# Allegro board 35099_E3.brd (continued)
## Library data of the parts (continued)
R240 R241 = RES: signal model: DEFAULT_RESISTOR_51000OHM_2_1
R243-R246 R248 R350 R353 R354 R356-R358 R360 R361 R365 R417-R422 = RES: signal model: RES_RC0402_25_DISCRETE_0.45_M_1_0
R249 R250 R362 R363 = RES: tolerance: 5%; signal model: DEFAULT_RESISTOR_10000OHM_2_1
R300-R307 R377-R380 R384-R398 = RES_3PIN: Tolerance: X; User Part Number: 470-80866; signal model: RES_3PIN_R603-X2_DISCRETE_0.6MM_0
RT1 = THERMISTOR: signal model: DEFAULT_RESISTOR_100000OHM_2_1
SH2-SH4 SH11-SH14 SH17-SH21 = RES_SHORT-2: signal model: DEFAULT_RESISTOR_0.001OHM_2_1
SW1-SW3 = SW_PB_4P
SW4 = SW_TC_SPST_4P
SW5 = SW_DIP-3
TP1-TP10 TP12-TP14 TP16 TP18 TP21-TP34 TP37-TP46 = TEST POINT L
TP11 TP15 TP17 TP19 TP20 = TESTLOOP
U1 = LPC432_BGA_100P
U2 U5 U10 U27 U28 = 74LVCH1T45_6P
U3 U26 = 74AVC2T45_8P
U4 U9 = 74AVC4TD245BQ_DHVQFN16
U6 = FXOS8700CQ_QFN_16P
U7 = NX3DV2567GU_XQFN_16P
U8 = WM8904CGEFL_QFN32
U12 U17 = TFA9894D_48P
U13 = NX5P3090UK_WLCSP12
U14 = LD1117AS18
U15 = 2-input_or
U16 U30 = NC7SZ14
U18 = MIMXRT685EVKA_176P
U19 = MX25UM51345GXD
U20 = PCA9420KBS_HVQFN24
U21 U22 = PRTR5V0U2X
U23 U25 = NCP692_6P
U24 = 74LVC07APW
U32 = 74LVC2G07
U34 = NTB0104BQ
U35 = NTB0102DP
U36 = NTS0102
U40 U41 = MIC_SPH0641LM4H-1_5P
U108 = APS6408L-OBx_BGA24L
Y1 = XTAL
Y2 = XTAL_13
Y3 = CRYSTAL
Y8 = OSC_ASFL

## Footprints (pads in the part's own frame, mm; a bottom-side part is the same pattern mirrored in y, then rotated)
0402_CC
  rect 0.457x0.508 smd: 1(-0.375,0) 2(0.375,0)
0603_CC
  rect 0.711x0.838 smd: 1(-0.65,0) 2(0.65,0)
BGA176_0P5_9X9
  round 0.229 smd: A1(-4,4) A2(-3.5,4) A3(-3,4) A5(-2,4) A7(-1,4) A9(0,4) A11(1,4) A13(2,4) A15(3,4) A16(3.5,4) A17(4,4) B1(-4,3.5) B2(-3.5,3.5) B3(-3,3.5) B5(-2,3.5) B6(-1.5,3.5) B7(-1,3.5) B9(0,3.5) B10(0.5,3.5) B11(1,3.5) B13(2,3.5) B14(2.5,3.5) B15(3,3.5) B16(3.5,3.5) B17(4,3.5) C1(-4,3) C2(-3.5,3) C3(-3,3) C4(-2.5,3) C5(-2,3) C7(-1,3) C9(0,3) C11(1,3) C13(2,3) C15(3,3) C16(3.5,3) C17(4,3) D2(-3.5,2.5) D5(-2,2.5) D6(-1.5,2.5) D7(-1,2.5) D8(-0.5,2.5) D9(0,2.5) D11(1,2.5) D12(1.5,2.5) D13(2,2.5) D15(3,2.5) E1(-4,2) E2(-3.5,2) E3(-3,2) E4(-2.5,2) E6(-1.5,2) E8(-0.5,2) E10(0.5,2) E12(1.5,2) E14(2.5,2) E15(3,2) E16(3.5,2) E17(4,2) F4(-2.5,1.5) F5(-2,1.5) F7(-1,1.5) F11(1,1.5) F13(2,1.5) F14(2.5,1.5) F16(3.5,1.5) G1(-4,1) G2(-3.5,1) G3(-3,1) G4(-2.5,1) G6(-1.5,1) G12(1.5,1) G14(2.5,1) G15(3,1) G16(3.5,1) G17(4,1) H2(-3.5,0.5) H5(-2,0.5) H8(-0.5,0.5) H9(0,0.5) H10(0.5,0.5) H13(2,0.5) H14(2.5,0.5) J1(-4,0) J2(-3.5,0) J3(-3,0) J4(-2.5,0) J8(-0.5,0) J10(0.5,0) J14(2.5,0) J15(3,0) J16(3.5,0) J17(4,0) K4(-2.5,-0.5) K5(-2,-0.5) K8(-0.5,-0.5) K9(0,-0.5) K10(0.5,-0.5) K13(2,-0.5) K16(3.5,-0.5) L1(-4,-1) L2(-3.5,-1) L3(-3,-1) L4(-2.5,-1) L6(-1.5,-1) L12(1.5,-1) L14(2.5,-1) L15(3,-1) L16(3.5,-1) L17(4,-1) M2(-3.5,-1.5) M4(-2.5,-1.5) M5(-2,-1.5) M7(-1,-1.5) M11(1,-1.5) M13(2,-1.5) M14(2.5,-1.5) N1(-4,-2) N2(-3.5,-2) N3(-3,-2) N4(-2.5,-2) N6(-1.5,-2) N8(-0.5,-2) N10(0.5,-2) N12(1.5,-2) N14(2.5,-2) N15(3,-2) N16(3.5,-2) N17(4,-2) P3(-3,-2.5) P5(-2,-2.5) P6(-1.5,-2.5) P7(-1,-2.5) P9(0,-2.5) P10(0.5,-2.5) P11(1,-2.5) P12(1.5,-2.5) P13(2,-2.5) P16(3.5,-2.5) R1(-4,-3) R2(-3.5,-3) R3(-3,-3) R5(-2,-3) R7(-1,-3) R9(0,-3) R11(1,-3) R13(2,-3) R14(2.5,-3) R15(3,-3) R16(3.5,-3) R17(4,-3) T1(-4,-3.5) T2(-3.5,-3.5) T3(-3,-3.5) T4(-2.5,-3.5) T5(-2,-3.5) T7(-1,-3.5) T8(-0.5,-3.5) T9(0,-3.5) T11(1,-3.5) T12(1.5,-3.5) T13(2,-3.5) T15(3,-3.5) T16(3.5,-3.5) T17(4,-3.5) U1(-4,-4) U2(-3.5,-4) U3(-3,-4) U5(-2,-4) U7(-1,-4) U9(0,-4) U11(1,-4) U13(2,-4) U15(3,-4) U16(3.5,-4) U17(4,-4)
CC0201
  rect 0.47x0.381 smd: 1(-0.343,0) 2(0.343,0)
CC0402_25
  round 0.635 smd: 1(-0.508,0) 2(0.508,0)
CC0402_TOL0P2
  rect 0.457x0.61 smd: 1(-0.475,0) 2(0.475,0)
CC0603_0402_NSP
  rect 1.016x1.168 smd: 1(-0.699,0) 2(0.699,0)
CC0603_0805_NSP
  rect 1.549x1.549 smd: 1(-0.965,0) 2(0.965,0)
CC0603_OV
  oval 0.889x1.143 smd: 1(-0.762,0) 2(0.762,0)
CC1210
  rect 1.778x2.845 smd: 1(-1.397,0) 2(1.397,0)
CON2_TB_5MM_10X7P5MM_TH
  rect 2.159x2.159 hole 1.295: 1(0,0)
  round 2.159 hole 1.295: 2(5,0)
CON3_SKT_DC_POWER
  rect 2.235x2.235 hole 1.6: 1(0,0)
  round 2.235 hole 1.6: 2(3.1,5) 3(6.2,0)
CON4_JACK_5X17
  round 0.254 hole 1.702 unplated: (0,2.5) (0,-4.5)
  rect 2.794x2.21 smd: 1(-3.7,3.6) 3(3.7,1.6)
  rect 2.794x2.794 smd: 2(-3.7,-5.8) 4(0.753,-9.9)
CON9_MICROAB_USB_SHELL_TH
  rect 1.803x1.905 smd: (-1.15,0) (1.15,0)
  rect 0.406x1.346 smd: 1(-1.3,2.8) 2(-0.65,2.8) 3(0,2.8) 4(0.65,2.8) 5(1.3,2.8)
  oval 1.067x1.27 hole 0.66x0.864: 6(2.225,3.125) 9(-2.225,3.125)
  rect 2.21x1.905 hole 1.499x0.838: 7(4.175,0) 8(-4.175,0)
CON_1X8_SKT_2P54_TH
  rect 1.702x1.702 hole 1.016: 1(0,0)
  round 1.702 hole 1.016: 2(0,-2.54) 3(0,-5.08) 4(0,-7.62) 5(0,-10.16) 6(0,-12.7) 7(0,-15.24) 8(0,-17.78)
CON_67_0P5_22X7P75_RA
  rect 1.194x2.743 smd: (-10.35,3.125) (10.35,3.125)
  round 0.254 hole 1.092 unplated: (-10,-1.375)
  round 0.254 hole 1.6 unplated: (10,-1.375)
  rect 0.305x1.549 smd: 1(-9.25,3.9) 2(-9,-3.65) 3(-8.75,3.9) 4(-8.5,-3.65) 5(-8.25,3.9) 6(-8,-3.65) 7(-7.75,3.9) 8(-7.5,-3.65) 9(-7.25,3.9) 10(-7,-3.65) 11(-6.75,3.9) 12(-6.5,-3.65) 13(-6.25,3.9) 14(-6,-3.65) 15(-5.75,3.9) 16(-5.5,-3.65) 17(-5.25,3.9) 18(-5,-3.65) 19(-4.75,3.9) 20(-4.5,-3.65) 21(-4.25,3.9) 22(-4,-3.65) 23(-3.75,3.9) 32(-1.5,-3.65) 33(-1.25,3.9) 34(-1,-3.65) 35(-0.75,3.9) 36(-0.5,-3.65) 37(-0.25,3.9) 38(0,-3.65) 39(0.25,3.9) 40(0.5,-3.65) 41(0.75,3.9) 42(1,-3.65) 43(1.25,3.9) 44(1.5,-3.65) 45(1.75,3.9) 46(2,-3.65) 47(2.25,3.9) 48(2.5,-3.65) 49(2.75,3.9) 50(3,-3.65) 51(3.25,3.9) 52(3.5,-3.65) 53(3.75,3.9) 54(4,-3.65) 55(4.25,3.9) 56(4.5,-3.65) 57(4.75,3.9) 58(5,-3.65) 59(5.25,3.9) 60(5.5,-3.65) 61(5.75,3.9) 62(6,-3.65) 63(6.25,3.9) 64(6.5,-3.65) 65(6.75,3.9) 66(7,-3.65) 67(7.25,3.9) 68(7.5,-3.65) 69(7.75,3.9) 70(8,-3.65) 71(8.25,3.9) 72(8.5,-3.65) 73(8.75,3.9) 74(9,-3.65) 75(9.25,3.9)
CON_MIC_38M_25_SM
  round 0.254 hole 2.388 unplated: (11.43,0)
  rect 0.432x1.27 smd: 1(5.715,-3.556) 2(5.715,3.556) 3(5.08,-3.556) 4(5.08,3.556) 5(4.445,-3.556) 6(4.445,3.556) 7(3.81,-3.556) 8(3.81,3.556) 9(3.175,-3.556) 10(3.175,3.556) 11(2.54,-3.556) 12(2.54,3.556) 13(1.905,-3.556) 14(1.905,3.556) 15(1.27,-3.556) 16(1.27,3.556) 17(0.635,-3.556) 18(0.635,3.556) 19(0,-3.556) 20(0,3.556) 21(-0.635,-3.556) 22(-0.635,3.556) 23(-1.27,-3.556) 24(-1.27,3.556) 25(-1.905,-3.556) 26(-1.905,3.556) 27(-2.54,-3.556) 28(-2.54,3.556) 29(-3.175,-3.556) 30(-3.175,3.556) 31(-3.81,-3.556) 32(-3.81,3.556) 33(-4.445,-3.556) 34(-4.445,3.556) 35(-5.08,-3.556) 36(-5.08,3.556) 37(-5.715,-3.556) 38(-5.715,3.556)
  round 1.397 hole 0.889: S1(-5.08,0) S2(-2.54,0) S3(0,0) S4(2.54,0) S5(5.08,0)
CON_SDCARD_28P9X29_SM_RA
  round 0.254 hole 1.499 unplated: (-12.675,-9.05) (11.525,-9.05)
  rect 0.991x1.499 smd: 1(6.325,15.26) 2(3.825,15.26) 3(0.475,15.26) 4(-1.175,15.26) 5(-3.675,15.26) 6(-6.175,15.26) 7(-8.605,15.26) 8(-10.305,15.26) 9(8.825,15.26) 10(2.125,15.26) 11(-13.655,15.26)
  rect 1.194x2.007 smd: G1(-14.175,-6.95) G2(13.825,-5.75)
CON_SKT1X6_TH
  rect 1.524x1.524 hole 1.041: 1(0,0)
  round 1.524 hole 1.041: 2(0,-2.54) 3(0,-5.08) 4(0,-7.62) 5(0,-10.16) 6(0,-12.7)
CON_SKT1X9_TH
  rect 1.651x1.651 hole 1.016: 1(0,0)
  round 1.651 hole 1.016: 2(0,-2.54) 3(0,-5.08) 4(0,-7.62) 5(0,-10.16) 6(0,-12.7) 7(0,-15.24) 8(0,-17.78) 9(0,-20.32)
DFN6_0P95_3X3
  rect 0.889x0.457 smd: 1(-1.469,0.95) 2(-1.469,0) 3(-1.469,-0.95) 4(1.469,-0.95) 5(1.469,0) 6(1.469,0.95)
  rect 1.676x2.591 smd: 7(0,0)
DFN1010N-6_0P35_1P15X1P05
  rect 0.356x0.178 smd: 1(-0.433,0.35) 2(-0.433,0) 3(-0.433,-0.35) 4(0.433,-0.35) 5(0.433,0) 6(0.433,0.35)
  rect 0.254x0.406 smd: 7(0,0.275) 8(0,-0.275)
DHVQFN14_3X2P5MM
  rect 0.914x0.279 smd: 1(-1.55,-0.25) 7(1.55,-0.25) 8(1.55,0.25) 14(-1.55,0.25)
  rect 0.279x0.914 smd: 2(-1,-1.3) 3(-0.5,-1.3) 4(0,-1.3) 5(0.5,-1.3) 6(1,-1.3) 9(1,1.3) 10(0.5,1.3) 11(0,1.3) 12(-0.5,1.3) 13(-1,1.3)
  rect 1.651x1.143 smd: 15(0,0)
DHVQFN16_0P5_3P6X2P6
  rect 0.305x0.838 smd: 1(-0.25,1.719) 8(-0.25,-1.719) 9(0.25,-1.719) 16(0.25,1.719)
  rect 0.838x0.305 smd: 2(-1.219,1.25) 3(-1.219,0.75) 4(-1.219,0.25) 5(-1.219,-0.25) 6(-1.219,-0.75) 7(-1.219,-1.25) 10(1.219,-1.25) 11(1.219,-0.75) 12(1.219,-0.25) 13(1.219,0.25) 14(1.219,0.75) 15(1.219,1.25)
  rect 1.143x2.159 smd: 17(0,0)
FBGA100_0P8_9X9
  round 0.406 smd: A1(-3.6,3.6) A2(-2.8,3.6) A3(-2,3.6) A4(-1.2,3.6) A5(-0.4,3.6) A6(0.4,3.6) A7(1.2,3.6) A8(2,3.6) A9(2.8,3.6) A10(3.6,3.6) B1(-3.6,2.8) B2(-2.8,2.8) B3(-2,2.8) B4(-1.2,2.8) B5(-0.4,2.8) B6(0.4,2.8) B7(1.2,2.8) B8(2,2.8) B9(2.8,2.8) B10(3.6,2.8) C1(-3.6,2) C2(-2.8,2) C3(-2,2) C4(-1.2,2) C5(-0.4,2) C6(0.4,2) C7(1.2,2) C8(2,2) C9(2.8,2) C10(3.6,2) D1(-3.6,1.2) D2(-2.8,1.2) D3(-2,1.2) D4(-1.2,1.2) D5(-0.4,1.2) D6(0.4,1.2) D7(1.2,1.2) D8(2,1.2) D9(2.8,1.2) D10(3.6,1.2) E1(-3.6,0.4) E2(-2.8,0.4) E3(-2,0.4) E4(-1.2,0.4) E5(-0.4,0.4) E6(0.4,0.4) E7(1.2,0.4) E8(2,0.4) E9(2.8,0.4) E10(3.6,0.4) F1(-3.6,-0.4) F2(-2.8,-0.4) F3(-2,-0.4) F4(-1.2,-0.4) F5(-0.4,-0.4) F6(0.4,-0.4) F7(1.2,-0.4) F8(2,-0.4) F9(2.8,-0.4) F10(3.6,-0.4) G1(-3.6,-1.2) G2(-2.8,-1.2) G3(-2,-1.2) G4(-1.2,-1.2) G5(-0.4,-1.2) G6(0.4,-1.2) G7(1.2,-1.2) G8(2,-1.2) G9(2.8,-1.2) G10(3.6,-1.2) H1(-3.6,-2) H2(-2.8,-2) H3(-2,-2) H4(-1.2,-2) H5(-0.4,-2) H6(0.4,-2) H7(1.2,-2) H8(2,-2) H9(2.8,-2) H10(3.6,-2) J1(-3.6,-2.8) J2(-2.8,-2.8) J3(-2,-2.8) J4(-1.2,-2.8) J5(-0.4,-2.8) J6(0.4,-2.8) J7(1.2,-2.8) J8(2,-2.8) J9(2.8,-2.8) J10(3.6,-2.8) K1(-3.6,-3.6) K2(-2.8,-3.6) K3(-2,-3.6) K4(-1.2,-3.6) K5(-0.4,-3.6) K6(0.4,-3.6) K7(1.2,-3.6) K8(2,-3.6) K9(2.8,-3.6) K10(3.6,-3.6)
HDR1X2_2P0_5P9X7P6
  rect 1.651x1.651 hole 1.016: 1(0,0)
  round 1.651 hole 1.016: 2(2,0)
HDR102
  rect 1.524x1.524 hole 1.016: 1(0,0)
  round 1.524 hole 1.016: 2(0,-2.54)
HDR103
  rect 1.524x1.524 hole 1.016: 1(0,0)
  round 1.524 hole 1.016: 2(0,-2.54) 3(0,-5.08)
HDR110
  rect 1.676x1.676 hole 1.016: 1(0,0)
  round 1.676 hole 1.016: 2(0,-2.54) 3(0,-5.08) 4(0,-7.62) 5(0,-10.16) 6(0,-12.7) 7(0,-15.24) 8(0,-17.78) 9(0,-20.32) 10(0,-22.86)
HDR205
  rect 1.676x1.676 hole 1.016: 1(0,0)
  round 1.676 hole 1.016: 2(2.54,0) 3(0,-2.54) 4(2.54,-2.54) 5(0,-5.08) 6(2.54,-5.08) 7(0,-7.62) 8(2.54,-7.62) 9(0,-10.16) 10(2.54,-10.16)
HDR205_10M_50_SM_K
  rect 0.737x2.794 smd: 1(-2.54,-2.032) 2(-2.54,2.032) 3(-1.27,-2.032) 4(-1.27,2.032) 5(0,-2.032) 6(0,2.032) 7(1.27,-2.032) 8(1.27,2.032) 9(2.54,-2.032) 10(2.54,2.032)
HDR210_FTSH_SM
  rect 2.794x0.737 smd: 1(-2.032,5.715) 2(2.032,5.715) 3(-2.032,4.445) 4(2.032,4.445) 5(-2.032,3.175) 6(2.032,3.175) 7(-2.032,1.905) 8(2.032,1.905) 9(-2.032,0.635) 10(2.032,0.635) 11(-2.032,-0.635) 12(2.032,-0.635) 13(-2.032,-1.905) 14(2.032,-1.905) 15(-2.032,-3.175) 16(2.032,-3.175) 17(-2.032,-4.445) 18(2.032,-4.445) 19(-2.032,-5.715) 20(2.032,-5.715)
HVQFN24_0P4_3P1X3P1_EP
  oval 0.711x0.203 smd: 1(-1.55,0.9) 2(-1.55,0.5) 4(-1.55,-0.5) 5(-1.55,-0.9) 13(1.55,-0.9) 14(1.55,-0.5) 16(1.55,0.5) 17(1.55,0.9)
  rect 0.711x0.406 smd: 3(-1.55,0) 15(1.55,0)
  rect 0.635x0.635 smd: 6(-1.517,-1.517) 12(1.517,-1.517) 18(1.517,1.517) 24(-1.517,1.517)
  oval 0.203x0.711 smd: 7(-0.9,-1.55) 8(-0.5,-1.55) 10(0.5,-1.55) 11(0.9,-1.55) 19(0.9,1.55) 20(0.5,1.55) 22(-0.5,1.55) 23(-0.9,1.55)
  rect 0.406x0.711 smd: 9(0,-1.55) 21(0,1.55)
  rect 1.905x1.905 smd: 25(0,0)
IND_1P8X1MM_SM
  rect 0.991x0.711 smd: 1(-0.845,0) 2(0.845,0)
IND_0402
  round 0.635 smd: 1(-0.508,0) 2(0.508,0)
IND_0603
  rect 0.991x0.813 smd: 1(-0.69,0) 2(0.69,0)
IND_1608
  rect 0.61x0.813 smd: 1(-0.7,0) 2(0.7,0)
IND_2016_2520_NSP
  rect 1.295x2.591 smd: 1(-1.05,0) 2(1.05,0)
IND_2016A
  rect 0.864x1.803 smd: 1(-0.835,0) 2(0.835,0)
JUMP1X4-6040
  rect 1.524x1.524 hole 1.016: 1(0,0)
  round 1.524 hole 1.016: 2(2.54,0) 3(5.08,0) 4(7.62,0)
JUMP2X7-6040
  rect 1.524x1.524 hole 1.016: 1(0,0)
  round 1.524 hole 1.016: 2(2.54,0) 3(0,-2.54) 4(2.54,-2.54) 5(0,-5.08) 6(2.54,-5.08) 7(0,-7.62) 8(2.54,-7.62) 9(0,-10.16) 10(2.54,-10.16) 11(0,-12.7) 12(2.54,-12.7) 13(0,-15.24) 14(2.54,-15.24)
LED_0603
  rect 0.838x0.787 smd: A(-0.775,0) C(0.775,0)
MH244-166T
  round 6.198 hole 4.216: 1(0,0)
MIC5_3P6X2P75MM
  round 0.254 hole 0.381 unplated: (0,-0.71)
  rect 0.711x0.508 smd: 1(-0.831,1.364) 2(-0.831,0.542) 4(0.831,0.542) 5(0.831,1.364)
  custom 0.405x0.405 smd: 3(-0.66,-0.71)
MIC_9MM_TH
  rect 1.549x1.549 hole 0.914: 1(0,0)
  round 1.549 hole 0.914: 2(0,2.54)
MSOP_8P_0P65_3X3MM
  rect 0.432x0.889 smd: 1(-0.975,-2.17) 2(-0.325,-2.17) 3(0.325,-2.17) 4(0.975,-2.17) 5(0.975,2.17) 6(0.325,2.17) 7(-0.325,2.17) 8(-0.975,2.17)
PBGA24_1_6X8MM
  round 0.33 smd: A2(-1,2) A3(0,2) A4(1,2) A5(2,2) B1(-2,1) B2(-1,1) B3(0,1) B4(1,1) B5(2,1) C1(-2,0) C2(-1,0) C3(0,0) C4(1,0) C5(2,0) D1(-2,-1) D2(-1,-1) D3(0,-1) D4(1,-1) D5(2,-1) E1(-2,-2) E2(-1,-2) E3(0,-2) E4(1,-2) E5(2,-2)
PQFN16_0P4_2P65X1P85
  rect 0.203x0.762 smd: 1(-0.6,-0.724)
  rect 0.203x0.66 smd: 2(-0.2,-0.775) 3(0.2,-0.775) 4(0.6,-0.775) 9(0.6,0.775) 10(0.2,0.775) 11(-0.2,0.775) 12(-0.6,0.775)
  rect 0.66x0.203 smd: 5(1.21,-0.6) 6(1.21,-0.2) 7(1.21,0.2) 8(1.21,0.6) 13(-1.21,0.6) 14(-1.21,0.2) 15(-1.21,-0.2) 16(-1.21,-0.6)
QFN5X3_0P5_3X3
  rect 0.813x0.305 smd: 1(-1.275,1) 2(-1.275,0.5) 3(-1.275,0) 4(-1.275,-0.5) 5(-1.275,-1) 9(1.275,-1) 10(1.275,-0.5) 11(1.275,0) 12(1.275,0.5) 13(1.275,1)
  rect 0.305x0.813 smd: 6(-0.5,-1.275) 7(0,-1.275) 8(0.5,-1.275) 14(0.5,1.275) 15(0,1.275) 16(-0.5,1.275)
QFN32_0P4_4P1SQ_2P8EP
  oval 0.762x0.203 smd: 1(-1.975,1.4) 8(-1.975,-1.4) 17(1.975,-1.4) 24(1.975,1.4)
  rect 0.762x0.203 smd: 2(-1.975,1) 3(-1.975,0.6) 4(-1.975,0.2) 5(-1.975,-0.2) 6(-1.975,-0.6) 7(-1.975,-1) 18(1.975,-1) 19(1.975,-0.6) 20(1.975,-0.2) 21(1.975,0.2) 22(1.975,0.6) 23(1.975,1)
  oval 0.203x0.762 smd: 9(-1.4,-1.975) 16(1.4,-1.975) 25(1.4,1.975) 32(-1.4,1.975)
  rect 0.203x0.762 smd: 10(-1,-1.975) 11(-0.6,-1.975) 12(-0.2,-1.975) 13(0.2,-1.975) 14(0.6,-1.975) 15(1,-1.975) 26(1,1.975) 27(0.6,1.975) 28(0.2,1.975) 29(-0.2,1.975) 30(-0.6,1.975) 31(-1,1.975)
  rect 2.794x2.794 smd: 33(0,0)
R603-X2
  oval 0.889x1.143 smd: 1(-0.762,0) 2(0.762,0) 3(2.286,0)
RC0402_25
  round 0.635 smd: 1(-0.508,0) 2(0.508,0)
RC0603_OV
  oval 0.889x1.143 smd: 1(-0.762,0) 2(0.762,0)
SC70-5
  rect 0.406x0.813 smd: 1(-0.65,-1.079) 2(0,-1.079) 3(0.65,-1.079) 4(0.65,1.079) 5(-0.65,1.079)
SH0402
  round 0.635 smd: 1(-0.508,0) 2(0.508,0)
SH0603
  rect 0.991x0.813 smd: 1(-0.8,0) 2(0.8,0)
SH_HDR102_BOTTOM
  rect 1.524x1.524 hole 1.016: 1(0,0)
  round 1.524 hole 1.016: 2(0,-2.54)
SKT2X2_TH_SSQ
  rect 1.524x1.524 hole 1.016: 1(0,0)
  round 1.524 hole 1.016: 2(-2.54,0) 3(0,-2.54) 4(-2.54,-2.54)
SKT2X6_100_TH_RA
  rect 1.651x1.651 hole 1.016: 1(0,0)
  round 1.651 hole 1.016: 2(2.54,0) 3(0,-2.54) 4(2.54,-2.54) 5(0,-5.08) 6(2.54,-5.08) 7(0,-7.62) 8(2.54,-7.62) 9(0,-10.16) 10(2.54,-10.16) 11(0,-12.7) 12(2.54,-12.7)
SOD123LF
  rect 1.219x1.27 smd: A(1.549,0) C(-1.549,0)
SOD523
  rect 0.61x0.813 smd: A(0.85,0) C(-0.85,0)
SOD-123
  rect 1.321x1.219 smd: A(-1.626,0) C(1.626,0)
SOT23_A
  rect 0.787x0.889 smd: 1(-0.94,-1.003) 2(0.94,-1.003) 3(0,1.003)
SOT143B
  rect 0.991x0.61 smd: 1(-0.75,-1)
  rect 0.508x0.61 smd: 2(0.95,-1) 3(0.95,1) 4(-0.95,1)
SOT223
  rect 1.194x2.21 smd: 1(-2.3,-3.1) 2(0,-3.1) 3(2.3,-3.1)
  rect 3.734x2.21 smd: 4(0,3.1)
SOT323_3
  rect 0.406x0.991 smd: 1(0.65,-1.06) 2(-0.65,-1.06) 3(0,1.06)
SOT363
  rect 0.406x0.508 smd: 1(-0.65,-0.95) 2(0,-0.95) 3(0.65,-0.95) 4(0.65,0.95) 5(0,0.95) 6(-0.65,0.95)
SOT1061
  rect 0.406x0.508 smd: 1(0.65,0.804) 2(-0.65,0.804)
  custom 0.337x0.337 smd: 3(0,-0.377)
SOT-363_0P65_SMT
  rect 0.762x0.381 smd: 1(-1.085,0.65) 2(-1.085,0) 3(-1.085,-0.65) 4(1.085,-0.65) 5(1.085,0) 6(1.085,0.65)
SSOP8_DCU
  rect 0.279x1.219 smd: 1(-0.75,-1.499) 2(-0.25,-1.499) 3(0.25,-1.499) 4(0.75,-1.499) 5(0.75,1.499) 6(0.25,1.499) 7(-0.25,1.499) 8(-0.75,1.499)
SW4_4P2X2P8_SM
  rect 0.914x1.016 smd: 1(-2.05,0.8) 2(2.05,0.8) 3(-2.05,-0.8) 4(2.05,-0.8)
SW4_SKRP
  rect 1.499x0.762 smd: 1(-2.3,1.075) 2(2.3,1.075) 3(-2.3,-1.075) 4(2.3,-1.075)
SW_DIP6_2P54_7P37X9P65MM_SM
  rect 3.175x1.778 smd: 1(-4.763,2.54) 2(-4.763,0) 3(-4.763,-2.54) 4(4.763,-2.54) 5(4.763,0) 6(4.763,2.54)
TEST_LOOP
  round 1.524 hole 1.016: 1(0,0)
TPAD_050
  round 1.27 smd: 1(0,0)
TSSOP8_A
  rect 1.448x0.457 smd: 1(-2.15,0.975) 2(-2.15,0.325) 3(-2.15,-0.325) 4(-2.15,-0.975) 5(2.15,-0.975) 6(2.15,-0.325) 7(2.15,0.325) 8(2.15,0.975)
TSSOP14
  rect 1.524x0.457 smd: 1(-2.959,1.951) 2(-2.959,1.3) 3(-2.959,0.65) 4(-2.959,0) 5(-2.959,-0.65) 6(-2.959,-1.3) 7(-2.959,-1.951) 8(2.959,-1.951) 9(2.959,-1.3) 10(2.959,-0.65) 11(2.959,0) 12(2.959,0.65) 13(2.959,1.3) 14(2.959,1.951)
unnamed#2
  round 1.016 smd: (0,0)
USB_MICRO_B_0P65_SM_RA
  round 0.254 hole 0.787 unplated: (-2.5,1.85) (2.5,1.85)
  rect 0.457x1.295 smd: 1(-1.3,2.95) 2(-0.65,2.95) 3(0,2.95) 4(0.65,2.95) 5(1.3,2.95)
  oval 1.143x1.803 hole 0.559x1.194: S1(-3.875,-0.9) S2(3.875,-0.9)
  oval 1.448x2.007 hole 0.838x1.397: S3(3.725,2.9) S4(-3.725,2.9)
WLCSP12_0P4_1P38X1P68MM_SMDP
  round 0.254 smd: A1(-0.4,0.6) A2(0,0.6) A3(0.4,0.6) B1(-0.4,0.2) B2(0,0.2) B3(0.4,0.2) C1(-0.4,-0.2) C2(0,-0.2) C3(0.4,-0.2) D1(-0.4,-0.6) D2(0,-0.6) D3(0.4,-0.6)
WLCSP48_0P4_2P51X3P55
  round 0.229 smd: A1(-1,1.235) A2(-0.6,1.235) A3(-0.2,1.235) A4(0.2,1.235) A5(0.6,1.235) A6(1,1.235) B1(-1,0.835) B2(-0.6,0.835) B3(-0.2,0.835) B4(0.2,0.835) B5(0.6,0.835) B6(1,0.835) C1(-1,0.435) C2(-0.6,0.435) C3(-0.2,0.435) C4(0.2,0.435) C5(0.6,0.435) C6(1,0.435) D1(-1,0.035) D2(-0.6,0.035) D3(-0.2,0.035) D4(0.2,0.035) D5(0.6,0.035) D6(1,0.035) E1(-1,-0.365) E2(-0.6,-0.365) E3(-0.2,-0.365) E4(0.2,-0.365) E5(0.6,-0.365) E6(1,-0.365) F1(-1,-0.765) F2(-0.6,-0.765) F3(-0.2,-0.765) F4(0.2,-0.765) F5(0.6,-0.765) F6(1,-0.765) G1(-1,-1.165) G2(-0.6,-1.165) G3(-0.2,-1.165) G4(0.2,-1.165) G5(0.6,-1.165) G6(1,-1.165) H1(-1,-1.565) H2(-0.6,-1.565) H3(-0.2,-1.565) H4(0.2,-1.565) H5(0.6,-1.565) H6(1,-1.565)
XSON8_0P5_3P1X2P1
  rect 0.813x0.279 smd: 1(-1.375,0.75) 2(-1.375,0.25) 3(-1.375,-0.25) 4(-1.375,-0.75) 5(1.375,-0.75) 6(1.375,-0.25) 7(1.375,0.25) 8(1.375,0.75)
XTAL2-3P2X1P5-SM
  rect 1.092x1.905 smd: 1(-1.25,0) 2(1.25,0)
XTAL4_3P3X2P6_SM_FL
  rect 1.499x1.194 smd: 1(-1.06,-0.8) 2(1.06,-0.8) 3(1.06,0.8) 4(-1.06,0.8)
XTL2_11P6X4P85_SM
  rect 5.588x2.032 smd: 1(-4.75,0) 2(4.75,0)
XTLOSC4_3P2X2P5MM_SM
  rect 1.397x1.194 smd: 1(-1.1,-0.8) 2(1.1,-0.8) 3(1.1,0.8) 4(-1.1,0.8)

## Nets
2V5_OUT: C50.1 C51.1 JS8.1 U14.2(VOUT)
3V3_LINK_CORE: C91.1 C93.1 C96.1 L13.1 U1.E4 U1.E5 U1.F4
3V3_OUT: C136.1 JS14.2 U23.4 U23.5(SNS)
3V3_OUT_USB1: C138.1 JS16.2 U25.4 U25.5(SNS)
5V_SYS: C90.1 D12.A J29.8 JS10.1
+2.5V_LINK: C23.1 C38.1 C92.1 C94.1 C95.1 C97.1 C98.1 C99.1 C100.1 C140.1 JP4.1 JS8.2 L13.2 R6.1 R24.2 R29.1 R30.2 R31.2 R32.1 R33.1 R37.1 R126.1 R127.1 TP1.1(TP) U1.B2 U1.C5 U1.D1 U1.D2 U1.F10 U1.K5 U2.1 U3.1 U4.1 U5.1 U9.1 U9.2 U9.7 U9.15 U10.1 U26.1
+5V: C83.1 C135.1 C137.1 D6.3(C) D7.3(C) JS10.2 TP13.1(TP) TP16.1(TP) U20.16(VIN) U23.1 U23.6 U25.1 U25.3 U25.6
+5V_EXT: C67.1 C77.1 C78.1 J6.1(VBUS) JP11.1 L8.1 U13.B1 U13.B2 U13.C1(VINT3)
+5V_LINK: C56.1 C60.1 D7.2 L1.2 R22.2 U14.3
AVDD: C35.1 L3.2 U8.23
GND: BH1.1 C1.2 C2.2 C3.2 C4.2 C5.2 C8.2 C9.2 C10.1 C11.2 C12.2 C13.2 C14.1 C16.1 C18.2 C19.2 C21.2 C22.1 C23.2 C24.2 C25.1 C26.2 C27.2 C28.2 C29.2 C30.2 C31.2 C32.2 C33.2 C34.2 C35.2 C36.1 C37.1 C38.2 C39.2 C40.2 C41.2 C42.2 C43.2 C44.2 C45.2 C46.2 C47.2 C48.2 C49.2 C50.2 C51.2 C52.2 C53.2 C54.2 C55.2 C56.2 C57.2 C58.2 C59.2 C60.2 C61.2 C62.2 C63.2 C64.2 C65.2 C66.2 C67.2 C69.2 C70.2 C71.2 C72.2 C73.2 C74.2 C75.2 C76.2 C77.2 C78.2 C79.2 C80.2 C81.2 C82.2 C83.2 C84.2 C85.2 C86.2 C87.2 C88.2 C89.2 C90.2 C91.2 C92.2 C93.2 C94.2 C95.2 C96.2 C97.2 C98.2 C99.2 C100.2 C101.2 C102.2 C103.2 C104.2 C105.2 C106.2 C107.2 C108.2 C109.2 C110.2 C111.2 C112.2 C113.2 C114.2 C115.2 C116.2 C117.2 C118.2 C119.2 C120.2 C121.2 C122.2 C123.2 C124.2 C125.2 C126.2 C127.2 C128.2 C129.2 C130.2 C131.2 C132.2 C133.2 C134.1 C135.2 C136.2 C137.2 C138.2 C139.1 C140.2 C143.2 C217.2 C218.2 C219.2 C250.2 C251.2 C252.2 C253.2 C316.2 C317.2 C319.2 C320.2 C321.2 C322.2 C328.2 C329.2 C330.2 C331.2 C332.2 C333.2 C336.2 C337.2 C338.2 D2.C(CATHODE) D3.3(DOUBLE_CATHODE) D4.3(DOUBLE_CATHODE) D11.C(CATHODE) D13.2 D14.3(DOUBLE_CATHODE) D15.C(CATHODE) D26.A J2.3 J2.5 J3.1 J4.1 J5.5 J5.S1 J5.S2 J5.S3 J5.S4 J6.5 J6.S1 J6.S2 J6.S3 J6.S4 J7.5 J7.6 J7.7 J7.8 J7.9 J16.3 J18.4 J19.3 J19.5 J19.15 J19.17 J19.19 J21.2 J24.2 J24.3 J25.1 J25.2 J26.1 J26.2 J28.7 J29.6 J29.7 J31.11 J31.12 J32.3 J32.6 J32.G1 J32.G2 J35.2 J35.4(B2) J36.9 J36.10 J38.5 J38.S1 J38.S2 J38.S3 J38.S4 J38.S5 J45.1 J45.7 J45.18 J45.33 J45.39 J45.45 J45.51 J45.57 J45.63 J45.69 J45.75 JP1.2 JP3.2 JP9.2 JS1.1 Q1.2(SOURCE) Q3.1 Q3.3 Q3.4(SOURCE2) Q3.5 Q3.8 Q4.1 Q4.4(SOURCE2) Q8.3 R4.2 R5.2 R8.2 R9.2 R12.2 R13.2 R15.2 R17.2 R19.2 R20.2 R21.2 R23.2 R25.2 R27.2 R38.2 R47.2 R53.1 R55.2 R61.2 R68.2 R81.2 R90.2 R93.2 R94.2 R95.2 R104.2 R135.2 R136.2 R141.2 R231.2 R377.3 R378.1 RT1.2 SW1.3 SW1.4 SW2.3 SW2.4 SW3.3 SW3.4 SW4.1 SW4.2 TP2.1(TP) TP11.1(PIN1) U1.C2 U1.C8 U1.D3 U1.D4 U1.D5 U1.F2 U1.G8 U1.J3 U1.J6 U2.2 U3.4 U4.8 U4.17 U5.2 U5.5 U6.3 U6.5 U6.12 U6.13 U7.1 U7.5 U7.6 U7.9 U7.15 U8.5 U8.9 U8.14 U8.17 U8.22 U8.33 U9.8 U9.10 U9.17 U10.2 U12.A4 U12.B4 U12.B5 U12.C2 U12.C5 U12.D2 U12.D3 U12.D4 U12.D5 U12.E2 U12.E3 U12.E4 U12.E5 U12.F1 U12.F2 U12.F3 U12.F4 U12.F5 U12.F6 U12.G4 U13.B3 U13.C3 U13.D3 U14.1 U15.3 U16.3 U17.A4 U17.B4 U17.B5 U17.C2 U17.C5 U17.D2 U17.D3 U17.D5 U17.E2 U17.E3 U17.E4 U17.E5 U17.F1 U17.F2 U17.F3 U17.F4 U17.F5 U17.F6 U17.G4 U18.C3 U18.D5 U18.D12 U18.D15 U18.E12 U18.E14 U18.F7 U18.F11 U18.G6 U18.G12 U18.H8(VSS_9) U18.H9 U18.H10 U18.J8 U18.J10 U18.K8 U18.K9 U18.K10 U18.L6 U18.L12 U18.M7 U18.M11 U18.M13 U18.N14 U18.P13 U19.B3 U19.C1 U19.E5(VSSQ2) U20.9 U20.21 U20.23 U20.24 U20.25 U21.1 U22.1 U23.2 U23.7 U24.7 U25.2 U25.7 U26.4 U26.5 U27.2 U28.2 U28.5 U30.3 U32.2 U34.7 U34.15 U35.2 U36.2 U40.3 U41.3 U108.B3 U108.C1 U108.E5(VSSQ_2) Y2.2 Y2.4 Y8.2
P1V8_CODEC: C21.1 C27.1 C30.1 C336.1 C337.1 J31.1 J31.2 JS2.1 L3.1 R377.1 R378.3 U8.6 U8.7 U40.5(VDD) U41.5(VDD)
P5V_TRG_JTAG: J19.11 J19.13 TP12.1(TP)
VBAT: C80.1 J21.1 R107.1 TP27.1(TP) U20.18
VBAT_BKUP: C131.1 R107.2 TP29.1(TP) U20.13
VBST/VDDP_1: C43.1 C44.1 C49.1 C53.1 U12.G5 U12.H1 U12.H2 U12.H3 U12.H5 U12.H6
VBST/VDDP_2: C61.1 C64.1 C70.1 C72.1 U17.G5 U17.H1 U17.H2 U17.H3 U17.H5 U17.H6
VBUS0_TARGET: R54.2 R55.1 U18.R16
VDD1V8: C103.1 C104.1 C106.1 C118.1 C123.1 JP28.1 U18.A13 U18.B11 U18.C16 U18.C17 U18.E15 U18.F13 U18.G14 U18.L4 U18.R15
VDD_ACCEL: C28.1 C29.1 JP15.2 U6.14
VDD_AMP: C41.1 C55.1 C57.1 C74.1 JP11.2 L4.1 L7.1 U12.C6 U17.C6
VDD_CODEC: C33.1 C329.1 C333.1 JS3.1 L2.1 R411.1 R412.1 U8.4 U35.3 U35.6 U36.3 U36.6
VDD_JACK: C75.1 C76.1 J24.1 JP11.3
VDD_LDO_3V3: C39.1 JP15.1 JS15.2 JS16.1 R50.1 R60.2 SH4.1 U27.6(VCCB) U28.6(VCCB)
VDD_LINK: C10.2 C12.1 C16.2 C25.2 C36.2 J2.1 JP2.2 R16.1 R41.1 R43.1 U2.6(VCCB) U3.8(VCCB) U5.6(VCCB) U10.6(VCCB)
VDD_MEM: C127.1 C128.1 C129.1 C130.1 C132.1 C133.1 C217.1 C218.1 C219.1 C317.1 JS12.1 R66.1 R69.1 R71.2 R240.1 R241.1 R362.1 R363.1 U19.B4 U19.D1 U19.E4 U108.B4 U108.D1 U108.E4
VDD_PMOD: C134.2 J36.11 J36.12(B6) JS9.1
VDD_RST: R132.2 U24.14 U32.5
VDD_TARGET: JS11.2 JS13.2 R1.1 R98.1 R123.1
VDDA_ADC1V8: C109.1 JP25.2 U18.E4
VDDA_AO: C101.1 C102.1 JP26.2 U18.C13 U18.D13
VDDA_BIAS: C338.1 JP24.2 U18.C4
VDDCORE: C107.1 C108.1 C112.1 C114.1 C115.1 C119.1 C125.1 C126.1 JP29.1 U18.C5 U18.D9 U18.F14 U18.J4 U18.J14 U18.P9 U18.R5 U18.R14
VDDE_A: C52.1 C63.1 C71.1 C328.1 JS7.1 U12.A3 U12.B3 U12.C3 U12.C4 U15.5(VCC) U16.5 U17.A3 U17.B3 U17.C3 U17.C4 U17.D4 U34.14(VCCB)
VDDIO: C105.1 C124.1 JP27.1 U18.N12 U18.P11 U18.P12
VDDIO1: C322.1 C330.1 C332.1 D5.A JP2.1 JP12.2 JP23.1 JP24.1 JS7.2 JS9.2 R10.1 R39.2 R58.1 R83.1 R84.1 R105.1 R116.1 R117.1 R130.1 R133.1 R137.1 R138.1 R139.1 R140.1 R145.1 R383.1 R409.1 R410.1 R413.1 R414.1 U7.14(VCC) U30.5 U35.7(VCCB) U36.7(VCCB)
VDDIO1_MCU: C110.1 C113.1 C117.1 JP23.2 U18.E6 U18.E8 U18.E10 U18.H13 U18.H14 U18.K13 U18.L14
ACC_INT1: R40.1 R138.2 U6.11
ACC_INT2: R137.2 TP37.1(TP) U6.9
ACCEL_RST_8700: R141.1 R144.2 U6.16
ALT_INT_AMP: JP6.3 U34.5
ALT_INT_CODEC: R48.1 R401.2
BOOT0_LED: R6.2 R7.1 U1.K2
BOOT1: R9.1 U1.K1
BOOT2: R29.2 U1.C6
BOOT3: R21.1 U1.B10
BRDG_INTR-ISP_DIR: R25.1 U1.J7 U4.10
BRIDGE_INTR-ISP: JP13.2 R36.1 R108.1
BRIDGE_L_INTR-ISP: R34.2 U1.J5
BRIDGE_L_MISO: U1.J1 U26.2
BRIDGE_L_MOSI: U1.J2 U4.6
BRIDGE_L_SCK: U1.K9 U4.4
BRIDGE_L_SSEL: U1.K10 U4.3
BRIDGE_UART_RXD: U1.G10 U9.4
BRIDGE_UART_TXD: U1.G7 U9.5
BT_REG_ON_3V3: C319.1 J45.54(W\_\D\I\S\A\B\L\E\2\) Q16.3 R227.2
BYP_8700: C31.1 U6.2
CARD_WR_PRT: J32.11(WP) R307.1 R308.2
CPCA: C20.1 U8.8
CPCB: C20.2 U8.10
CRST_8700: C143.1 U6.8
CS_AP: R248.2 U108.A3
CS_MX: R350.2 U19.C2
DCDC_3V3: C85.1 J28.8 J29.2 J29.4 JS15.1
DQS_AP: R246.2 U108.C3
DQS_MX: R353.2 U19.C3
ELECTRET_MIC: D14.1 P1.2 R42.1 R49.3
FC0_RXD: J16.2 R50.2 U28.4
FC0_TXD: J16.1 U27.4
FC1_CTS_SDA_SSEL0: J31.14 J47.4 R396.3 R408.2
FC1_SCK: J47.1 R394.3
FC1_TXD_SCL_MISO: J47.2 R395.3
FC2_SCK: J47.5 R397.3
FC4_CTS_SDA_SSEL0: J47.9 R398.3
FC5_CTS: J45.34 R212.2
FC5_RTS: J45.36 R213.2
FC5_RXD: J45.22 R210.2
FC5_TXD: J45.32 R211.2
HP_OUTL: C11.1 C15.1 D3.1 J4.2 U8.13
HP_OUTR: C2.1 C17.1 D3.2 J4.3 U8.15
I2C_SA0_8700: R135.1 R139.2 U6.7
I2C_SA1_8700: R136.1 R140.2 U6.10
I2PIO2_0-SD0_D(0)_SCL: JS6.1 R126.2 U1.D6
I2PIO2_0-SD0_D(0)_SDA: JS5.1 R127.2 U1.E6
I2S_ALT_INT: U15.4 U34.10
I2S_BCLK_AMP: U12.B1 U12.B2 U17.B1 U17.B2 U34.12
I2S_BCLK_CODEC: R215.2 R400.2 U8.29
I2S_DAI_AMP: U12.D1 U17.D1 U34.11
I2S_DAI_CODEC: R217.2 R404.2 U8.31
I2S_DAO_AMP: JP7.3 U12.C1 U17.C1
I2S_DAO_CODEC: R218.2 R402.2 U8.32 U35.4
I2S_WS_AMP: U12.A1 U17.A1 U34.13
I2S_WS_CODEC: R216.2 R399.2 U8.30
IF_DETECT: J2.9 JS1.2 R28.1
IF_JTAG_TDI: D13.1 J2.8 R26.2
IF_RST: D13.3 J2.10(B5) J19.10 JP17.1 R148.2 SH11.1 U24.9
IF_TCK_SWCLK: D13.6(K5) J2.4 J19.4 JP18.1 R104.1 SH13.1 U7.3
IF_TDO_SWO: D13.4 J2.6 J19.6 R41.2 SH12.1 U5.4 U7.11
INB_1: L4.2 U12.G1 U12.G2 U12.G3
INB_2: L7.2 U17.G1 U17.G2 U17.G3
INT1_AMP: U12.A5 U15.1
INT2_AMP: U15.2 U17.A5
INT_B: R85.2 U18.A15 U20.10
JTAG_RESET: U1.D10 U10.3
JTAG_RESET_TXEN: R47.1 U1.G9 U10.5
JTAG_TDI: U1.J10 U3.3
JTAG_VREF: J19.1 J38.12 J38.14 R58.2 R130.2
LDO1_OUT: C84.1 JP26.1 R3.1 R67.1 R70.1 R82.1 R85.1 R124.1 R132.1 R134.1 R148.1 R149.1 TP17.1(PIN1) U20.12
LDO2_OUT: C82.1 JP12.3 JP27.2 JS11.1 R89.1 R308.1 R309.1 R310.1 TP15.1(PIN1) U20.15
LDO_ENABLE: JP22.2 U18.A16
LED_BLUE: D8.C(CATHODE) Q3.6 Q3.7
LED_GREEN: D10.C(CATHODE) Q4.3 Q4.8
LED_RED: D9.C(CATHODE) Q4.6 Q4.7
LININL: C7.1 U8.26
LININL_JACK: C7.2 C8.1 D4.1 D14.2 J3.2 P1.1(OUT) R19.1
LININR: R49.2 U8.24
LININR_JACK: C4.1 C6.2 D4.2 J3.3 R4.1
LINK2_ISP_BOOT: JP1.1 U1.C10
LX1: L11.1 U20.22
LX2: L12.1 U20.1
M2_32K_3V3: J45.50 R200.2 R423.2
M2_SD_CDM: R202.1 R303.3
M2_SD_CLK: R201.1 R302.3
M2_SD_DAT0: R203.1 R301.3
M2_SD_DAT1: R204.1 R300.3
M2_SD_DAT2: R205.1 R305.3
M2_SD_DAT3: R206.1 R304.3
M2_SD_RST_B: R208.1 R306.3
M2_SD_WK_B: R207.1 R307.3
M2_USB_DN: J45.5 R222.1
M2_USB_DP: J45.3 R221.1
MCLK_CODEC: R403.2 U8.28 U35.5
MEM_1V8: R249.1 R250.1
MICBIAS: C32.1 R42.2 U8.20
MICVDD: C26.1 L2.2 U8.19
MODESEL0: R70.2 R81.1 U18.C15 U20.7
MODESEL1: R67.2 R68.1 U18.B16 U20.8
NRESET_OSPI: R69.2 R128.2 R351.1 R373.1 TP34.1(TP) U24.10 U24.12(O)
NRESET_OSPI_AP: R242.2 R372.2 R373.2 TP40.1(TP) U32.6
NRESET_PB: C1.1 R2.1 R3.2 U24.1
NRESET_POR: JS17.2 R106.2 U24.5
NRESET_TRGT: JP14.2 JP16.3 Q8.1 R124.2 R125.1 TP32.1(TP) TP39.1(TP) U16.2 U18.B15 U24.2 U24.4 U24.6 U24.8 U24.11 U30.2 U32.1
NTRST_LINK2: R33.2 TP3.1(TP) U1.B4
ON_B: JP16.2 U20.4
ON_B_SW: JP16.1 R89.2 SW4.3 SW4.4
OUTN_1: C54.1 J11.2(B) L6.2 R57.2 R59.2
OUTN_2: C73.1 J20.2(B) L10.2 R64.2 R65.2
OUTP_1: C45.1 J11.1 L5.2 R51.2 R52.2
OUTP_2: C65.1 J20.1 L9.2 R62.2 R63.2
P0_0: JP6.2 U18.G1
P0_0_CODEC_ALT_IN: JP6.1 R401.1
P0_1_FC0_TX: R147.2 U9.12 U18.G2 U27.3
P0_2_FC0_RX: JP21.2 R146.2 U18.G4
P0_2_FC0_RX_EXT: JP21.3 U28.3
P0_2_FC0_RX_LINK: JP21.1 R46.2
P0_3: J1.3 J45.58 R110.1 R415.2 U18.H2
P0_4: J1.5 J45.60 R416.2 U18.J1
P0_5_ADC0_0: R99.2 U18.F4
P0_6_ADC0_8: R100.2 U18.E1
P0_7_I2S_CLK: R394.1 R400.1 TP10.1(TP) U34.3
P0_8_I2S_WS: R395.1 R399.1 TP9.1(TP) U34.2
P0_9_CODEC_DAI: JP8.1 R404.1
P0_9_I2S_DAI: JP8.3 U34.4
P0_9_I2S_DATA: J47.3 JP8.2 U18.L3
P0_10: C5.1 R11.2 R396.1 SW2.1 SW2.2
P0_11: J1.10(B5) J31.13 R407.2 U18.L1
P0_12: J1.7 Q15.1(SOURCE) R229.2 U18.E3
P0_13: J1.6 Q16.1(SOURCE) R228.2 U18.G3
P0_14: Q4.5 R397.1
P0_15_FC2_SCL: J47.6 JS6.2 R113.1 U18.A5
P0_16_FC2_SDA: J47.7 JS5.2 R115.1 U18.D6
P0_17_FC2_SDA: J30.5 J47.8 R73.1 SH2.2 U18.D7
P0_18_FC2_SCL: J30.6 R72.1 SH3.2 U18.B7
P0_19_ADC0_2: R101.2 U18.A1
P0_20_ADC0_10: R102.2 U18.B2
P0_21: J19.12 SH17.2 U18.C7
P0_22: J19.14 SH21.2 U18.D8
P0_23_CODEC_DAO: JP7.1 R402.1 U35.1
P0_23_I2S_DATA_TX: J19.16 JP7.2 SH20.2 U18.C9
P0_24: J19.18 SH19.2 U18.B9
P0_25: J19.20 SH18.2 U18.A9
P0_26: Q3.2 U18.A2
P0_27: J27.4 U18.B3
P0_28: J27.3 U18.D11
P0_29_FC4_TXD: R79.1 U18.B10
P0_30_FC4_RXD: R80.1 U18.C11
P0_31: Q4.2 R398.1
P1_0: J27.5 U18.E17
P1_1: C3.1 R10.2 SW1.1 SW1.2 U18.G15
P1_2: J27.7 U18.A7
P1_3_SPI_CLK: R74.1 U18.G16
P1_4_SPI_MISO: R75.1 R211.1 U18.G17
P1_5_SPI_MOSI: JP30.1 R76.1 R210.1 U18.J16
P1_6_SPI_SS0: R77.1 R212.1 U18.J17
P1_7: J28.2 R213.1 TP41.1(TP) U18.J15 U32.3
P1_7_RST: R144.3 TP42.1(TP) U32.4(2Y)
P1_8: J27.8 R209.1 R231.1 U18.B5
P1_9: J28.1 U18.B1
P1_10_MCLK: J27.6 R403.1 TP8.1(TP) U18.K16 U35.8
P1_11_SPI_CLK: R385.2 U18.L2
P1_11_SPI_CLK_A: R114.2 R385.3 U4.13
P1_12_SPI_MISO: R386.2 U18.M2
P1_12_SPI_MISO_A: R112.2 R386.3 U26.7
P1_13_SPI_MOSI: R387.2 U18.N1
P1_13_SPI_MOSI_A: R111.2 R387.3 U4.11
P1_14_SPI_SS0: R388.2 U18.N2
P1_14_SPI_SS0_A: R109.2 R388.3 U4.14
P1_15: JP13.3 R86.2 SW5.6 U18.N3
P1_16: JP13.1 R87.2 SW5.5 U18.M4
P1_17: R88.2 SW5.4 U18.N4
P1_18_OSPI_CLK0: R245.1 U18.T9
P1_19_OSPI_SSEL0: R240.2 R247.1 R248.1 U18.T4
P1_20_OSPI_D0: R243.2 U18.T5
P1_21_OSPI_D1: R417.2 U18.U5
P1_22_OSPI_D2: R418.2 U18.P6
P1_23_OSPI_D3: R419.2 U18.P7
P1_24_OSPI_D4: R244.2 U18.T7
P1_25_OSPI_D5: R420.2 U18.U7
P1_26_OSPI_D6: R421.2 U18.R7
P1_27_OSPI_D7: R422.2 U18.T8
P1_28_OSPI_DQS: R246.1 U18.U9
P1_29_OSPI_B_SCK: R352.1 U18.U3
P1_30_SD0_CLK: R302.2 U18.P10
P1_31_SD0_CMD: R303.2 U18.R9
P2_0_SD0_D0: R301.2 U18.R11
P2_1_SD0_D1: R300.2 U18.T11
P2_2_SD0_D2: R305.2 U18.U11
P2_3_SD0_D3: R304.2 U18.T12
P2_4_SD0_WR_PRT: R307.2 TP21.1(TP) U18.T13
P2_5_SD0_D4: TP24.1(TP) U18.U13
P2_6_SD0_D5: TP25.1(TP) U18.U15
P2_7_SD0_D6: TP26.1(TP) U18.U16
P2_8_SD0_D7: TP14.1(TP) U18.U17
P2_9_SD0_CD: J32.10 R310.2 TP22.1(TP) U18.R13
P2_10_SD0_RST_N: R306.2 U18.T15
P2_11_SD0_VOLT: J1.1 TP23.1(TP) U18.T16
P2_12: J1.4 R131.2 TP33.1(TP) U18.T3 U24.13
P2_13: J1.2 U18.T1
P2_14: J1.9 U18.C1
P2_15: J1.8 U18.E2
P2_16_PDM_CLK01: R379.2 U18.R1
P2_17_PDM_CLK23: R389.2 U18.U1
P2_17_PDM_CLK23_A: J31.5 R389.3
P2_18_PDM_CLK45: R390.2 U18.R2
P2_18_PDM_CLK45_A: J31.7 R390.3
P2_19_PDM_CLK67: R384.2 U18.T2
P2_19_PDM_CLK67_A: J31.9 R384.3
P2_20_PDM_DATA01: R380.2 U18.U2
P2_21_PDM_DATA23: R393.2 U18.R3
P2_21_PDM_DATA23_A: J31.6 R393.1
P2_22_PDM_DATA45: R391.2 U18.P3
P2_22_PDM_DATA45_A: J31.8 R391.3
P2_23_PDM_DATA67: R392.2 U18.P5
P2_23_PDM_DATA67_A: J31.10 R392.3
P2_24_SWO: U7.12 U18.L16
P2_25_SWD_CLK: U7.4 U18.L17
P2_26_SWDIO: D13.5 J2.2 J19.2 JP19.1 R105.2 SH14.1 U18.L15
P2_27_USB1_OVERCURRENTN: R133.2 U13.A2 U18.M14
P2_28_USB1_PWRENA: Q1.1 R383.2 U18.N15
P2_29_I3C0_SCL: J18.1 R406.1 R409.2 R413.2 R423.1 TP7.1(TP) U12.A6 U17.A6 U18.N17 U36.1
P2_30_I3C0_SDA: J18.2 R118.1 R405.1 R410.2 R414.2 TP6.1(TP) U12.B6 U17.B6 U18.P16 U36.8
P2_31_I3C0_PUR: J18.3 R118.2 U18.B6
PDM_CLK01_EXT: J31.3 R379.3
PDM_CLK01_ONBOARD: R379.1 U40.4 U41.4
PDM_DATA01_EXT: J31.4 R380.3
PDM_DATA01_ONBOARD: R380.1 U40.1 U41.1
PIO0_7-FC1_SCK: R394.2 U18.J2
PIO0_8-FC1_TXD_SCL_MISO: R395.2 U18.K4
PIO0_10-FC1_CTS_SDA_SSELN0: R396.2 U18.J3
PIO0_14-FC2_SCK: R397.2 U18.A3
PIO0_31-FC4_CTS_SDA_SSELN0: R398.2 U18.A11
QSPI_B_CS0: R66.2 R350.1 R364.2 R384.1
QSPI_B_DATA0: R354.1 R385.1
QSPI_B_DATA1: R355.1 R386.1
QSPI_B_DATA2: R71.1 R356.1 R387.1
QSPI_B_DATA3: R357.1 R388.1
QSPI_B_DATA4: R358.1 R389.1
QSPI_B_DATA5: R359.1 R390.1
QSPI_B_DATA6: R360.1 R391.1
QSPI_B_DATA7: R361.1 R392.1
QSPI_B_DQS: R353.1 TP44.1(TP)
RESET_AMP: U12.E1 U16.4(Y) U17.E1
RESET_FXO: R144.1 U30.4(Y)
RST_AP: R241.2 R242.1 U108.A4
RST_MX: R351.2 U19.A4
RTCXIN: C69.1 U18.B17 Y3.2
RTCXOUT: C62.1 U18.A17 Y3.1
SCL: R84.2 TP30.1(TP) U18.E16 U20.5
SCL_CODEC: R406.2 R411.2 U8.2 U36.4
SCLK_AP: R245.2 U108.B2
SCLK_MX: R352.2 U19.B2
SD_CLK: J32.5 R302.1
SD_CMD: J32.2 R303.1 R309.2
SD_DAT0: J32.7 R301.1
SD_DAT1: J32.8 R300.1
SD_DAT2: J32.9 R305.1
SD_DAT3: J32.1 R304.1
SD_RST_N: R90.1 R123.2 R306.1 U23.3
SDA: R83.2 TP31.1(TP) U18.F16 U20.6
SDA_CODEC: R45.1 R405.2 R412.2 U36.5
SEL_ON_DMIC_1: R377.2 U40.2
SEL_ON_DMIC_2: R378.2 U41.2
SIO0_AP: R243.1 U108.D3
SIO0_MX: R354.2 U19.D3
SIO1_AP: R417.1 U108.D2
SIO1_MX: R355.2 U19.D2
SIO2_AP: R418.1 U108.C4
SIO2_MX: R356.2 U19.C4
SIO3_AP: R419.1 U108.D4
SIO3_MX: R357.2 U19.D4
SIO4_AP: R244.1 U108.D5
SIO4_MX: R358.2 U19.D5
SIO5_AP: R420.1 U108.E3
SIO5_MX: R359.2 U19.E3
SIO6_AP: R421.1 U108.E2
SIO6_MX: R360.2 U19.E2
SIO7_AP: R422.1 U108.E1
SIO7_MX: R361.2 U19.E1
SW1_OUT: C86.1 JP29.2 L11.2 TP19.1(PIN1) U20.19
SW2_OUT: C22.2 C37.2 C40.1 C46.1 C66.1 C88.1 C139.2 C316.1 C331.1 JP10.1 JP12.1 JP20.1 JP25.1 JP28.2 JS2.2 JS3.2 JS12.2 L12.2 Q15.2 Q16.2 R11.1 R86.1 R87.1 R88.1 R128.1 R131.1 R132.3 R146.1 R147.1 R228.1 R229.1 R372.1 R407.1 R408.1 R415.1 R416.1 TP20.1(PIN1) U4.16(VCCB) U9.16(VCCB) U12.A2 U17.A2 U20.3 U26.8(VCCB) U27.1 U27.5 U28.1 U34.1 U34.8
SW2_OUT_MCU: C111.1 C116.1 C120.1 C121.1 C122.1 JP20.2 U18.F5 U18.H5 U18.K5 U18.M5 U18.N6 U18.N8 U18.N10
SWDCLK_LINK2: R8.1 TP5.1(TP) U1.H2
SWDIO_LINK2: TP4.1(TP) U1.C4
SYSRST_B: R82.2 U20.11 U24.3
TAB: U14.4
TCK_SWCLK: U1.H10 U3.2
TDO_SWO: U1.J8 U5.3
TEMP_SEN: RT1.1 TP28.1(TP) U20.14
TMS_SWDIO: U1.K4 U2.3
TMS_SWDIO_TXEN: R20.1 U1.J4 U2.5
USB0_DM_TRGT: J7.2 R222.2 U18.T17 U22.3
USB0_DP_TRGT: J7.3 R221.2 U18.R17 U22.2
USB1_VDD3V3: SH4.2 U18.N16
USB_DM_LINK: J5.2 U1.E2 U21.3
USB_DP_LINK: J5.3 U1.E1 U21.2
USB_HS_HOST_VBUS: C42.1 C47.1 C48.1 FB1.2 J7.1(VBUS) U13.C2 U13.D1 U13.D2 U22.4(VCC)
USB_HS_VBUS_TRGT: D6.2 FB1.1 R54.1
USB_ID: R14.2 U1.F1
USB_ID_LINK: J5.4 R14.1
USB_VBUS_LINK: R22.1 U1.E3
USDHC_SPWR: C89.1 C250.1 C251.1 C252.1 C253.1 C321.1 D26.C J32.4 J45.2 J45.4 J45.72 J45.74 JS14.1 R121.1 R224.2 R225.2 R226.1 R227.1 Y8.4(VDD)
V_LED: JS13.1 R92.1 R96.1 R97.1
VMIDC: C34.1 U8.21(VMIDC)
VREF_H: C68.1 JP10.2 U18.D2
VREF_L: C68.2 JP9.1 U18.C2
VSN_1: R59.1 U12.D6
VSN_2: R65.1 U17.D6
VSP_1: R51.1 U12.E6(VSP/TEST3)
VSP_2: R62.1 U17.E6(VSP/TEST3)
VSYS: C79.1 C81.1 C87.1 TP18.1(TP) U20.2 U20.17 U20.20
WL_REG_ON_3V3: C320.1 J45.56 Q15.3 R226.2
XTALIN: C59.1 R56.1 U18.B14 Y2.1
XTALOUT: C58.1 R56.2 U18.B13 Y2.3
N16965957: C19.1 U8.11
N16965996: C18.1 U8.12
N16974908: J36.1 R109.1
N16974910: J36.2 R108.2
N16974934: J36.3 R111.1
N16974944: J36.4 R110.2
N16974979: J36.5 R112.1
N16974981: J36.6 R113.2
N16975000: J36.7 R114.1
N16975002: J36.8 R115.2
N16975069: J35.1 R106.1
N17023483: D9.A R96.2
N17023485: D8.A R92.2
N17023487: D10.A R97.2
N17103807: R46.1 U9.13
N17103888: JP4.2 R23.1 U4.9 U9.9
N17103964: R37.2 U4.2 U4.7 U4.15
N17104052: R34.1 U4.5
N17104054: R36.2 U4.12
N17136364: R13.1 U1.F3
N17136422: C13.1 U1.B1 Y1.2
N17136435: R31.1 U1.A6
N17136473: R32.2 U1.A4
N17136502: R30.1 U1.B6
N17136518: C14.2 U1.C1 Y1.1
N17202709: R125.2 U7.8
N17202739: JP3.1 R39.1 U7.2
N17208284: R28.2 U1.A10
N17208314: R5.1 U1.J9
N17208318: R15.1 U1.F9
N17208322: R12.1 U1.F8
N17208326: R17.1 U1.C9
N17337786: R35.1 U3.7
N17337788: JP18.2 R35.2
N17337803: R26.1 U3.6
N17337821: R24.1 U3.5
N17337994: R16.2 R18.1 U2.4
N17338012: JP19.2 R18.2
N17338109: R43.2 R44.1 U10.4
N17338127: JP17.2 R44.2
N17340148: D5.C JP2.3
N17344064: D2.A R7.2
N17759955: J28.10 R72.2
N17759973: J28.9 R73.2
N17759990: J29.3 JP14.1
N17760012: J28.6 R74.2
N17760030: D12.C J29.5
N17760042: J28.5 R75.2
N17760075: J28.4 R76.2
N17760099: J28.3 R77.2
N17760234: J30.1 R99.1
N17760260: J30.2 R100.1
N17760297: J30.3 R101.1
N17760315: J30.4 R102.1
N17760343: J27.2 R79.2
N17760363: J27.1 R80.2
N17774863: R93.1 SW5.1
N17774865: R94.1 SW5.2
N17774867: R95.1 SW5.3
N17792148: R45.2 U8.3
N17792155: R48.2 U8.1
N17851401: C6.1 R49.1
N17855943: L5.1 R52.1 U12.H4
N17855945: L6.1 R57.1 U12.G6
N17886052: L9.1 R63.1 U17.H4
N17886097: L10.1 R64.1 U17.G6
N18503998: JS17.1 R134.2
N18526070: C24.1 R145.2 U6.1(VDDIO)
N18526135: R117.2 SH3.1 U6.4
N18526137: R116.2 SH2.1 U6.6
N18526318: JP30.2 R40.2
N19506203: R2.2 SW3.1 SW3.2
N19508206: D1.A R1.2
N19508231: D1.C(CATHODE) Q8.2(SOURCE)
N19515068: D7.1 L8.2
N19515078: C9.1 J5.1(VBUS) L1.1 U21.4(VCC)
N19515258: J7.4 TP38.1(TP)
N19519270: R53.2 U13.A3
N19519289: Q1.3 R60.1 U13.A1
N19526530: JP22.1 R149.2
N19526548: JP22.3 R61.1
N19527680: D15.A R121.2
N19531396: D11.A R98.2
N19546738: R251.1 TP43.1(TP)
N19546803: R249.2 U108.A2
N19546823: R250.2 U108.A5
N19546843: R251.2 U108.B1
N19546881: R247.2 U108.C2
N19798378: J38.6 SH17.1
N19798386: J38.38 SH21.1
N19798394: J38.28 SH20.1
N19798402: J38.26 SH19.1
N19798410: J38.24 SH18.1
N19799787: J38.9 SH11.2
N19799813: J38.11 SH12.2
N19799835: J38.15 SH13.2
N19799857: J38.17 SH14.2
N19830189: R363.2 U19.A2
N19830205: R365.1 U19.B1
N19830207: R365.2 TP45.1(TP)
N19830220: R364.1 U19.A3
N19830414: R362.2 U19.A5
N19896770: J45.9 R201.2
N19896842: J45.11 R202.2
N19896868: J45.13 R203.2
N19896897: J45.15 R204.2
N19896926: J45.17 R205.2
N19896944: J45.19 R206.2
N19896964: J45.21 R207.2
N19896972: J45.23 R208.2
N19896981: D23.C(CATHODE) J45.6
N19897044: D22.C(CATHODE) J45.16
N19897050: D23.A R225.1
N19897088: J45.20 R209.2
N19897150: D22.A R224.1
N19897259: J45.8 R215.1
N19897289: J45.10 R216.1
N19897307: J45.12 R217.1
N19897327: J45.14 R218.1
N19898667: R200.1 Y8.3
N20219970: R393.3 TP46.1(TP)
N169660511: C15.2 R27.1
N169660621: C17.2 R38.1

Pads without a net: D6 1; J2 7; J3 4; J4 4; J6 2 3 4; J19 7 8 9; J29 1; J35 3; J38 1 2 3 4 7 8 10 13 16 18 19 20 21 22 23 25 27 29 30 31 32 33 34 35 36 37; J45 35 37 38 40 41 42 43 44 46 47 48 49 52 53 55 59 61 62 64 65 66 67 68 70 71 73; U1 A1 A2 A3 A5 A7 A8 A9 B3 B5 B7 B8 B9 C3 C7 D7 D8 D9 E7 E8 E9 E10 F5 F6 F7 G1 G2 G3 G4 G5 G6 H1 H3 H4 H5 H6 H7 H8 H9 K3 K6 K7 K8; U6 15; U7 7 10 13 16; U8 16 18 25 27; U9 3 6 11 14; U16 1; U19 B5 C5; U26 3 6; U30 1; U34 6 9; U108 B5 C5; Y8 1

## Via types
v1: diameter 0.457, hole 0.203, TOP to BOTTOM, 1290 vias
v2: diameter 0.305, hole 0.152, TOP to BOTTOM, 66 vias
v3: diameter 0.356, hole 0.203, TOP to BOTTOM, 26 vias

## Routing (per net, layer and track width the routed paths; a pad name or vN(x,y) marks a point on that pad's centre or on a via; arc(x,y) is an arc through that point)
3V3_LINK_CORE: length 9.5
  TOP w0.254: U1.E5 U1.E4 v3(131.22,109.73) ; U1.F4 v3(131.22,110.53)
  BOTTOM w0.381: C91.1 132.18,113.54 132.54,113.18 132.54,112.26 131.55,111.27 C93.1
  BOTTOM w0.508: C93.1 131.22,110.9 v3(131.22,110.53) v3(131.22,109.73) 130.99,109.5 C96.1 ; L13.1 132.2,114.22 C91.1
5V_SYS: length 173.1
  TOP w0.508: D12.A 25.37,10.16 30.61,10.16 31.39,9.38 C90.1 J29.8
  BOTTOM w0.508: J29.8 31.39,8.07 33.65,10.33 80.18,10.33 90.16,20.31 125.21,20.31 141.22,36.32 141.22,56.26 142.75,57.78 142.75,70.1 JS10.1
+2.5V_LINK: length 35.4
  TOP w0.254: R6.1 v1(130.45,117.96) ; U1.D2 v3(132.82,108.13) ; U4.1 116.84,99.37 C23.1 ; U1.B2 v3(132.82,106.53) ; R29.1 v1(126.87,101.41) ; R127.1 128.23,99.71 v1(128.6,99.34) 128.95,99.68 R126.1 ; R24.2 99.34,104.55 v1(98.86,105.03) ; v1(134.77,115.16) 133.78,116.15 TP1.1 ; U1.K5 v3(130.42,112.93) ; R33.1 v1(131.95,101.41) ; U1.D1 v3(133.62,108.13) ; R31.2 v1(129.16,101.41) ; U1.F10 v3(125.62,110.53) ; U1.C5 v3(130.42,107.33) ; R32.1 v1(130.81,101.41) ; R30.2 v1(128.02,101.41)
  TOP w0.305: v1(120.24,93.05) U9.7 ; U10.1 106.81,90.7 v1(107.62,90.7) ; U9.1 118.26,89.26 C38.1 ; U9.2 v1(120.17,90.55) ; U5.1 102.36,97.37 v1(102.36,97.97) ; U26.1 120.34,95.71 120.45,95.59 C140.1 ; v1(109.61,106.06) U2.1 ; U9.15 v1(115.85,90.55)
  TOP w0.381: v1(117.2,98.27) C23.1 ; U3.1 106.61,100.93 v1(106.45,101.09) ; v1(121.5,94.84) C140.1 ; v1(118.77,88.04) C38.1
  TOP w0.508: R37.1 v1(121.64,100.33)
  BOTTOM w0.254: C100.1 133.05,106.3 v3(132.82,106.53) ; v3(125.62,110.53) 125.53,110.62 C94.1 ; v3(133.62,108.13) 133.68,108.19 C98.1 ; C92.1 130.1,113.25 v3(130.42,112.93) ; C99.1 129.77,106.68 v3(130.42,107.33) ; v3(132.82,108.13) 133.72,109.03 C95.1
  BOTTOM w0.381: C97.1 135.61,109.18 C98.1
  BOTTOM w0.508: L13.2 134.19,115.75 v1(134.77,115.16)
+5V: length 65.1
  TOP w0.203: U20.16 122.56,53.31 v1(122.21,53.67)
  TOP w0.254: C83.1 121.73,54.15 v1(122.21,53.67)
  L3_IN1 w0.508: v1(107.95,53.34) 108.46,53.34 111.89,56.77 119.11,56.77 v1(122.21,53.67)
  L4_IN2 w0.508: JS10.2 136.53,73.91 132.08,69.47 132.08,65.52 124.16,57.6 120.6,57.6 120.02,57.02 109.09,57.02 107.95,55.88 v1(107.95,53.34)
+5V_EXT: length 179.8
  TOP w0.508: C77.1 C78.1 JP11.1
  BOTTOM w0.508: v1(140.46,66.07) 140.46,58.42 138.81,56.77 138.81,35.69 125.22,22.1 58.67,22.1 51.44,29.34 51.44,39.5 45.97,44.96 34.67,44.96 29.46,50.16 29.46,54.86 24.64,59.69 JP11.1
+5V_LINK:
  vias: v1(119.43,71.62) v1(120.17,72.77) v1(120.31,70.89) v1(120.88,71.75) v1(121.64,71.49) v1(122.61,71.78) v1(141.81,105.05) v1(142.14,106.12) v1(142.34,105.54) v1(145.8,75.36) v1(146.94,75.39) v1(147.14,74.75) v1(147.68,74.4) v1(147.9,75.01)
AVDD: length 6.3
  TOP w0.203: 38.39,93.66 38.73,94 U8.23
  TOP w0.508: L3.2 36.78,89.96 C35.1 37.59,91.57 38.15,92.13 38.15,93.42 38.39,93.66
GND: length 53.3
  TOP w0.203: U12.F6 v2(43.94,76.58) ; v1(43.13,97.66) 42.8,97.34 U8.9 ; U12.A4 v2(46.34,77.78) ; U17.F6 v2(43.94,65.66) ; U12.F1 v2(43.94,79.38) ; U17.A4 v2(46.34,66.86) ; U17.F1 v2(43.94,68.45)
  TOP w0.229: U8.5 41.6,95.2 U8.33 40.8,94.4 U8.22
  TOP w0.254: J45.57 v1(73.08,37.16) ; U16.3 51.17,71.9 v1(51.34,72.08) ; C28.2 80.34,94.35 C29.2 80.34,95.25 v1(79.63,95.25) ; J45.1 v1(59.08,37.16) ; C336.2 v1(8.14,9.33) ; J45.7 v1(60.58,36.96) ; U20.25 U20.9 v1(125.51,51.05) ; U20.25 U20.21 ; U20.25 122.16,50.15 U20.23 ; J45.51 v1(71.58,37.16) ; C62.2 v1(101.57,70.81) ; v1(54.88,101.15) 54.59,100.85 U36.2 ; U34.15 45.44,83.35 U34.7 ; U20.24 v1(120.69,49.54) ; v1(46.94,77.38) 47.66,77.38 C52.2 ; J45.33 v1(67.08,37.08) ; C46.2 v1(48.51,80.28) ; J45.69 v1(76.08,37.16) ; v1(139.89,16.89) 139.88,16.88 U24.7 ; J45.63 v1(74.58,37.16) ; J32.6 v1(117.08,29.07) ; J45.39 v1(68.58,37.16) ; J45.18 v1(63.33,31.93) ; v1(50.31,96.38) C330.2 C329.2 ; R61.2 v1(116.41,68.11) ; C42.2 v1(142.95,83.31) ; v1(123.73,29.03) 123.73,29.03 J32.3 ; R378.1 v1(105.81,3.99) ; J45.75 v1(77.58,36.57) ; J45.45 v1(70.08,37.16)
  TOP w0.508: D26.A v1(149.41,17.09) ; C87.2 v1(123.35,45.03) ; C321.2 v1(148.16,18.09) ; J29.7 29.87,6.39 C90.2
  BOTTOM w0.254: D13.2 106.68,115.42 106.31,115.05 v1(106.31,113.96)
  vias: v1(0.76,113.03) v1(0.76,104.14) v1(0.76,98.04) v1(0.76,91.44) v1(0.76,85.34) v1(0.76,77.72) v1(0.76,70.1) v1(0.76,64.01) v1(0.76,56.9) v1(0.76,51.31) v1(0.76,45.97) v1(0.76,42.16) v1(0.76,38.35) v1(1.02,20.32) v1(1.02,14.48) v1(7.11,78.74) v1(7.37,84.07) v1(7.37,74.17) v1(7.37,68.58) v1(7.62,90.68) v1(7.87,115.57) v1(8.13,121.16) v1(9.4,6.48) v1(9.78,48.01) v1(9.91,37.08) v1(9.91,35.31) v1(9.91,33.78) v1(9.91,31.75) v1(9.91,30.23) v1(9.91,28.45) v1(9.91,26.67) v1(9.91,25.15) v1(9.91,22.61) v1(9.91,19.05) v1(9.91,12.45) v1(10.16,42.93) v1(10.16,4.06) v1(10.54,108.33) v1(10.57,107.57) v1(11.2,4.13) v1(11.68,119.25) v1(11.81,1.91) v1(12.7,121.16) v1(12.7,83.82) v1(12.7,74.17) v1(12.7,68.83) v1(12.95,78.74) v1(13.46,114.81) v1(13.46,46.99) v1(13.46,42.93) v1(13.46,40.89) v1(13.46,37.08) v1(13.46,35.31) v1(13.46,31.75) v1(13.46,30.23) v1(13.46,28.45) v1(13.46,26.92) v1(13.46,25.15) v1(13.46,22.61) v1(13.46,19.3) v1(13.59,120.78) v1(13.61,117.22) v1(13.72,12.7) v1(15.49,119.25) v1(16,46.99) v1(16.43,59.54) v1(16.76,0.76) v1(17.02,85.34) v1(17.02,42.93) v1(17.27,78.74) v1(17.27,73.91) v1(17.53,98.3) v1(17.91,59.44) v1(18.03,102.62) v1(18.29,121.16) v1(18.54,46.99) v1(19.94,57.91) v1(20.07,37.85) v1(20.32,42.93) v1(21.08,46.99) v1(21.34,19.3) v1(21.59,12.95) v1(22.02,59.31) v1(22.16,112.26) v1(22.86,0.76) v1(23.11,121.16) v1(23.11,79.5) v1(23.11,74.17) v1(23.11,68.33) v1(23.37,107.19) v1(23.37,102.62) v1(23.37,98.3) v1(23.37,93.98) v1(23.37,85.09) v1(23.62,42.93) v1(24.64,56.13) v1(25.15,46.99) v1(26.16,37.85) v1(26.8,56.13) v1(26.92,71.12) v1(27.18,107.19) v1(27.18,102.62) v1(27.69,98.3) v1(27.69,93.98) v1(28.19,108.97) v1(28.19,107.4) v1(28.83,8.89) v1(28.96,0.76) v1(29.15,116.54) v1(29.21,121.16) v1(29.25,115.04) v1(29.21,73.91) v1(30.23,37.85) v1(30.48,79.11) v1(30.49,67.96) v1(30.57,77.06) v1(30.56,65.91) v1(30.9,95.82) v1(31.28,98.58) v1(31.5,82.3) v1(31.5,71.63) v1(32,115.06) v1(32.09,92.41) v1(32.3,93.89) v1(32.59,119.18) v1(33.53,0.76) v1(33.78,37.85) v1(34.29,93.09) v1(34.33,91.57) v1(34.47,95.26) v1(34.8,121.16) v1(34.8,117.47) v1(34.8,8.13) v1(35.5,104.41) v1(35.65,103) v1(36.02,87) v1(37.34,83.06) v1(37.67,99.97) v1(37.85,8.13) v1(38.01,88.34) v1(38.04,71.12) v1(38.06,90.37) v1(38.11,69.43) v1(38.33,97.64) v1(38.29,68.21) v1(38.32,65.98) v1(38.35,83.79) v1(38.51,81.36) v1(38.48,79.83) v1(38.66,96.65) v1(39,73.49) v1(39.37,121.16) v1(39.62,0.76) v1(40.13,8.13) v1(41.2,101.45) v1(42.42,101.57) v1(42.93,8.13) v1(43.15,112.24) v1(44.2,0.76) v1(44.96,106.17) v1(45.21,110.74) v1(45.47,8.13) v1(45.94,65.06) v1(45.97,121.16) v1(46.08,118.11) v1(46.2,94.74) v1(46.76,96.8) v1(46.76,95.78) v1(47.14,66.26) v1(47.75,90.68) v1(47.75,8.13) v1(48.77,0.76) v1(48.9,75.06) v1(48.9,72.01) v1(49.02,69.05) v1(49.02,67.56) v1(49.11,120.78) v1(49.06,116.71) v1(49.86,114.94) v1(50.42,93.22) v1(50.8,65.79) v1(50.8,65.02) v1(50.93,90.17) v1(51.32,77.11) v1(51.56,65.79) v1(51.56,65.02) v1(52.45,78.23) v1(52.47,65.79) v1(52.9,82.55) v1(53.47,53.85) v1(53.62,116.75) v1(53.87,120.87) v1(53.98,92.71) v1(54.23,87.63) v1(54.74,73.15) v1(54.89,115.16) v1(55.75,32.13) v1(55.75,29.21) v1(56.39,85.09) v1(56.77,58.8) v1(57.02,49.53) v1(57.28,32.13) v1(57.28,29.21) v1(57.53,52.45) v1(57.66,92.71) v1(57.78,35.43) v1(58.29,41.27) v1(58.57,29.71) v1(58.82,29.07) v1(59.05,25.27) v1(59.69,67.44) v1(59.82,46.61) v1(59.94,28.07) v1(60.45,52.45) v1(60.45,50.67) v1(60.45,48.51) v1(60.64,97.79) v1(61.09,25.27) v1(61.09,23.24) v1(61.21,35.69) v1(61.59,93.09) v1(63.04,52.82) v1(63.37,93.09) v1(63.5,46.61) v1(63.63,59.31) v1(63.72,36.61) v1(64.54,49.32) v1(64.77,93.09) v1(64.9,59.94) v1(65.17,28.44) v1(65.28,39.5) v1(65.66,25.27) v1(65.66,23.24) v1(66.04,93.09) v1(66.93,42.16) v1(67.04,54.82) v1(67.06,47.37) v1(67.31,57.78) v1(67.44,63.25) v1(67.69,25.27) v1(67.82,67.56) v1(67.94,51.32) v1(67.94,28.45) v1(68.71,32) v1(69.72,71.5) v1(69.85,57.78) v1(70.74,32) v1(70.87,72.64) v1(71.25,56.52) v1(71.25,25.27) v1(71.63,34.54) v1(71.88,72.64) v1(72.26,28.45) v1(72.52,87.76) v1(72.54,77.33) v1(72.64,47.24) v1(72.77,53.98) v1(72.9,72.26) v1(73.15,67.94) v1(73.66,120.9) v1(73.66,28.83) v1(73.66,25.27) v1(73.79,23.24) v1(75.69,52.32) v1(75.82,56.64) v1(76.2,77.22) v1(76.33,45.72) v1(76.33,43.05) v1(77.22,34.16) v1(77.47,52.32) v1(77.47,50.29) v1(77.47,41.19) v1(77.88,98.71) v1(77.85,97.76) v1(77.98,57.53) v1(78.11,59.1) v1(78.23,55.24) v1(78.49,31.62) v1(78.74,45.72) v1(78.74,43.05) v1(78.74,41.15) v1(79.12,75.82) v1(79.5,58.67) v1(79.5,52.45) v1(79.5,31.62) v1(79.76,105.08) v1(79.88,91.31) v1(80.01,38.86) v1(80.16,77.33) v1(80.4,44.74) v1(80.52,61.59) v1(80.52,59.31) v1(81.41,77.44) v1(81.41,41.19) v1(81.53,91.31) v1(81.53,23.24) v1(82.04,59.82) v1(82.04,31.62) v1(82.7,77.33) v1(82.68,45.76) v1(82.8,36.32) v1(82.93,87.76) v1(83.06,61.59) v1(83.32,42.59) v1(83.31,10.67) v1(83.82,76.71) v1(83.95,87.76) v1(83.95,28.96) v1(84.07,23.24) v1(84.53,55.32) v1(84.45,39.75) v1(84.71,59.82) v1(85.22,48.77) v1(85.6,68.71) v1(85.6,67.69) v1(85.6,56.26) v1(85.88,101.21) v1(85.85,99.63) v1(85.85,59.82) v1(85.86,49.7) v1(86.36,45.76) v1(87.63,85.34) v1(87.63,47.62) v1(88.27,47.67) v1(88.52,55.16) v1(88.93,111.79) v1(89.03,82.3) v1(89.15,120.9) v1(89.15,117.35) v1(89.53,40.77) v1(89.66,16.76) v1(89.79,29.59) v1(89.79,23.24) v1(89.92,76.75) v1(89.92,37.08) v1(90.33,79.96) v1(90.88,111.91) v1(91.57,82.3) v1(92.06,107.39) v1(92.11,106.57) v1(93.09,47.37) v1(93.22,120.9) v1(93.22,117.35) v1(93.47,48.77) v1(93.85,41.02) v1(93.98,37.08) v1(93.98,30.86) v1(93.98,23.24) v1(93.98,21.21) v1(93.98,19.05) v1(94.23,50.8) v1(94.49,53.47) v1(94.61,51.94) v1(94.74,47.37) v1(95.25,107.31) v1(95.63,41.02) v1(95.63,23.24) v1(95.63,21.21) v1(95.63,19.05) v1(95.66,94.48) v1(95.76,30.86) v1(96.65,86.11) v1(97.09,96.9) v1(97.41,41.02) v1(97.41,23.24) v1(97.41,21.21) v1(97.41,19.05) v1(97.54,120.9) v1(97.54,117.35) v1(97.54,113.03) v1(97.47,94.41) v1(97.54,37.08) v1(97.54,30.86) v1(98.25,94.12) v1(98.33,71.07) v1(98.42,92.58) v1(98.42,91.44) v1(98.53,98.21) v1(99.06,84.33) v1(99.31,30.86) v1(99.31,28.96) v1(99.64,100.99) v1(100.08,60.75) v1(100.77,91.5) v1(100.97,43.43) v1(101.25,67.93) v1(101.47,104.9) v1(101.6,116.84) v1(101.98,110.62) v1(102.03,89.94) v1(102.62,28.96) v1(103,107.47) v1(103,94.61) v1(103.12,98.81) v1(103.25,121.03) v1(103.43,106.05) v1(103.38,23.24) v1(103.38,21.21) v1(103.38,19.05) v1(103.76,84.58) v1(103.89,110.36) v1(104.14,1.02) v1(104.43,50.87) v1(104.41,8.82) v1(104.53,80.3) v1(104.65,113.16) v1(104.65,58.84) v1(104.78,114.55) v1(104.91,56.3) v1(105.16,87.5) v1(105.16,86.74) v1(105.54,92.33) v1(105.92,99.95) v1(105.92,17.14) v1(106.05,101.73) v1(106.05,23.24) v1(106.3,41.91) v1(106.81,98.68) v1(106.81,47.03) v1(106.93,45.59) v1(106.93,38.86) v1(107.06,111.89) v1(107.19,108.08) v1(107.19,84.88) v1(107.31,41.15) v1(107.44,103.63) v1(107.44,97.97) v1(107.7,91.95) v1(107.83,50.84) v1(107.97,37.2) v1(107.95,6.99) v1(108.2,118.05) v1(108.33,93.85) v1(108.46,103.25) v1(108.97,75.86) v1(108.97,45.72) v1(108.98,43.79) v1(109.35,111.89) v1(109.35,35.18) v1(109.47,118.03) v1(109.47,107.95) v1(109.6,23.24) v1(109.87,88.98) v1(109.98,60.58) v1(109.98,59.44) v1(109.98,53.85) v1(110.24,36.07) v1(110.24,17.14) v1(110.24,8.76) v1(110.74,1.02) v1(110.87,98.42) v1(110.87,96.9) v1(111,109.35) v1(111,36.83) v1(112.01,120.9) v1(112.02,71.9) v1(112.14,110.49) v1(112.27,104.52) v1(112.39,41.15) v1(112.52,66.04) v1(112.52,63.88) v1(112.74,100.14) v1(112.8,81.97) v1(112.9,57.78) v1(113.11,95.61) v1(113.06,84.48) v1(113.28,105.54) v1(113.8,76.62) v1(114.02,94.61) v1(114.17,99.01) v1(114.17,42.93) v1(114.3,53.34) v1(114.3,52.58) v1(114.3,49.15) v1(114.68,85.8) v1(115.32,115.44) v1(115.32,105.66) v1(115.44,97.21) v1(115.57,114.05) v1(115.62,77.14) v1(115.57,57.78) v1(115.72,88.75) v1(115.95,94.87) v1(116,93.32) v1(115.95,64.52) v1(116.13,85.85) v1(116.19,71.31) v1(116.59,36.83) v1(116.73,73.14) v1(116.84,53.34) v1(116.84,52.58) v1(116.9,120.89) v1(116.85,116.78) v1(117.34,104.22) v1(117.86,1.02) v1(118.03,95.07) v1(118.11,104.27) v1(118.11,16.51) v1(118.24,53.21) v1(118.49,80.4) v1(118.53,77.58) v1(118.49,63.88) v1(118.49,44.07) v1(118.58,118.71) v1(118.92,98.98) v1(118.9,93.95) v1(119,104.27) v1(119,47.37) v1(119.76,68.2) v1(120.13,85.86) v1(120.17,111.66) v1(120.27,108.36) v1(120.42,110.49) v1(120.52,105.97) v1(120.62,97.21) v1(120.6,88.75) v1(121.41,118.62) v1(121.39,116.17) v1(121.37,79.46) v1(121.45,56.97) v1(121.54,68.2) v1(121.54,66.17) v1(121.79,85.85) v1(121.92,93.83) v1(122,90.65) v1(122.17,96.39) v1(122.3,78.79) v1(122.34,56.97) v1(122.94,118.94) v1(123.33,79.53) v1(123.51,77.06) v1(123.99,78.31) v1(124.21,66.17) v1(124.59,68.11) v1(124.71,106.17) v1(124.71,104.01) v1(124.71,16.26) v1(124.71,1.02) v1(124.84,115.95) v1(124.82,79.49) v1(124.88,77.17) v1(125.09,73.79) v1(125.7,120.32) v1(125.73,117.98) v1(125.73,27.3) v1(126.36,73.79) v1(126.36,56.64) v1(126.92,50.75) v1(127.25,27.3) v1(127.69,86.79) v1(128.14,62.48) v1(128.17,118.14) v1(129.03,81.66) v1(129.39,49.04) v1(129.62,93.01) v1(129.67,68.07) v1(130.05,80.64) v1(130.81,77.22) v1(130.94,31.24) v1(131.19,114.43) v1(131.83,7.37) v1(132.08,85.6) v1(132.08,16.38) v1(132.08,1.02) v1(132.33,89.79) v1(133.1,77.72) v1(133.35,31.24) v1(133.6,83.31) v1(133.83,101.89) v1(133.99,111.38) v1(133.99,27.18) v1(134.58,114.48) v1(135.13,48.9) v1(135.13,46.86) v1(135.13,44.58) v1(135.38,96.52) v1(135.84,70.43) v1(135.89,64.52) v1(135.89,62.48) v1(135.89,36.58) v1(136.02,9.14) v1(136.32,117.68) v1(136.4,48.9) v1(136.4,46.86) v1(136.4,44.58) v1(137.03,10.67) v1(137.03,7.75) v1(137.13,80.24) v1(137.06,78.49) v1(137.41,38.35) v1(137.41,36.58) v1(137.85,78.49) v1(137.87,79.48) v1(138.18,64.52) v1(138.18,62.48) v1(138.18,59.69) v1(138.18,9.14) v1(138.43,114.2) v1(138.48,111.38) v1(138.68,87.38) v1(138.68,1.02) v1(138.94,101.35) v1(139.12,80.92) v1(139.45,64.52) v1(139.45,62.48) v1(139.45,59.69) v1(139.7,85.09) v1(139.83,38.35) v1(139.95,96.52) v1(139.95,76.45) v1(140.08,46.86) v1(140.08,43.69) v1(140.46,8.26) v1(140.8,81.09) v1(140.97,101.35) v1(140.97,75.56) v1(141.4,107.16) v1(142.04,114.33) v1(142.24,46.86) v1(142.24,44.2) v1(142.37,107.19) v1(142.75,118.11) v1(143.03,104.62) v1(143.21,103) v1(143.46,112.01) v1(143.87,109.25) v1(144.02,96.52) v1(144.15,39.24) v1(144.68,31.36) v1(144.78,87.88) v1(144.88,112.06) v1(145.03,1.02) v1(145.29,24.89) v1(145.59,110.67) v1(145.8,113.54) v1(146.18,89.15) v1(146.18,83.06) v1(146.3,76.83) v1(146.56,110.95) v1(146.69,70.61) v1(147.19,82.68) v1(147.7,22.73) v1(147.72,14.34) v1(148.08,81.79) v1(148.84,113.28) v1(148.84,41.27) v1(148.97,46.45) v1(150.5,79.12) v1(150.95,48.12) v1(150.92,47.31) v1(150.97,48.94) v1(151.11,110.09) v1(151.11,107.69) v1(151.13,101.85) v1(151.13,97.03) v1(151.13,93.22) v1(151.13,80.52) v1(151.13,76.2) v1(151.14,69.78) v1(151.14,67.38) v1(151.26,42.04) v1(151.38,45.72) v1(151.51,34.42) v2(90.37,67.54) v2(91.47,67.02) v2(91.97,63.52) v2(92.47,66.02) v2(92.47,65.02) v2(92.47,64.02) v2(92.97,66.02) v2(93.47,65.02) v2(93.47,64.02) v2(94.47,67.02) v2(94.47,66.02) v2(94.97,66.52) v2(94.97,63.52) v2(95.47,64.02) v2(95.47,63.02) v2(96.97,67.52) v3(127.22,111.33) v3(127.22,107.33) v3(128.82,112.93) v3(130.42,108.13) v3(131.22,108.13) v3(132.02,112.93) v3(132.02,108.13) v3(132.82,110.53) v3(132.82,107.33)
